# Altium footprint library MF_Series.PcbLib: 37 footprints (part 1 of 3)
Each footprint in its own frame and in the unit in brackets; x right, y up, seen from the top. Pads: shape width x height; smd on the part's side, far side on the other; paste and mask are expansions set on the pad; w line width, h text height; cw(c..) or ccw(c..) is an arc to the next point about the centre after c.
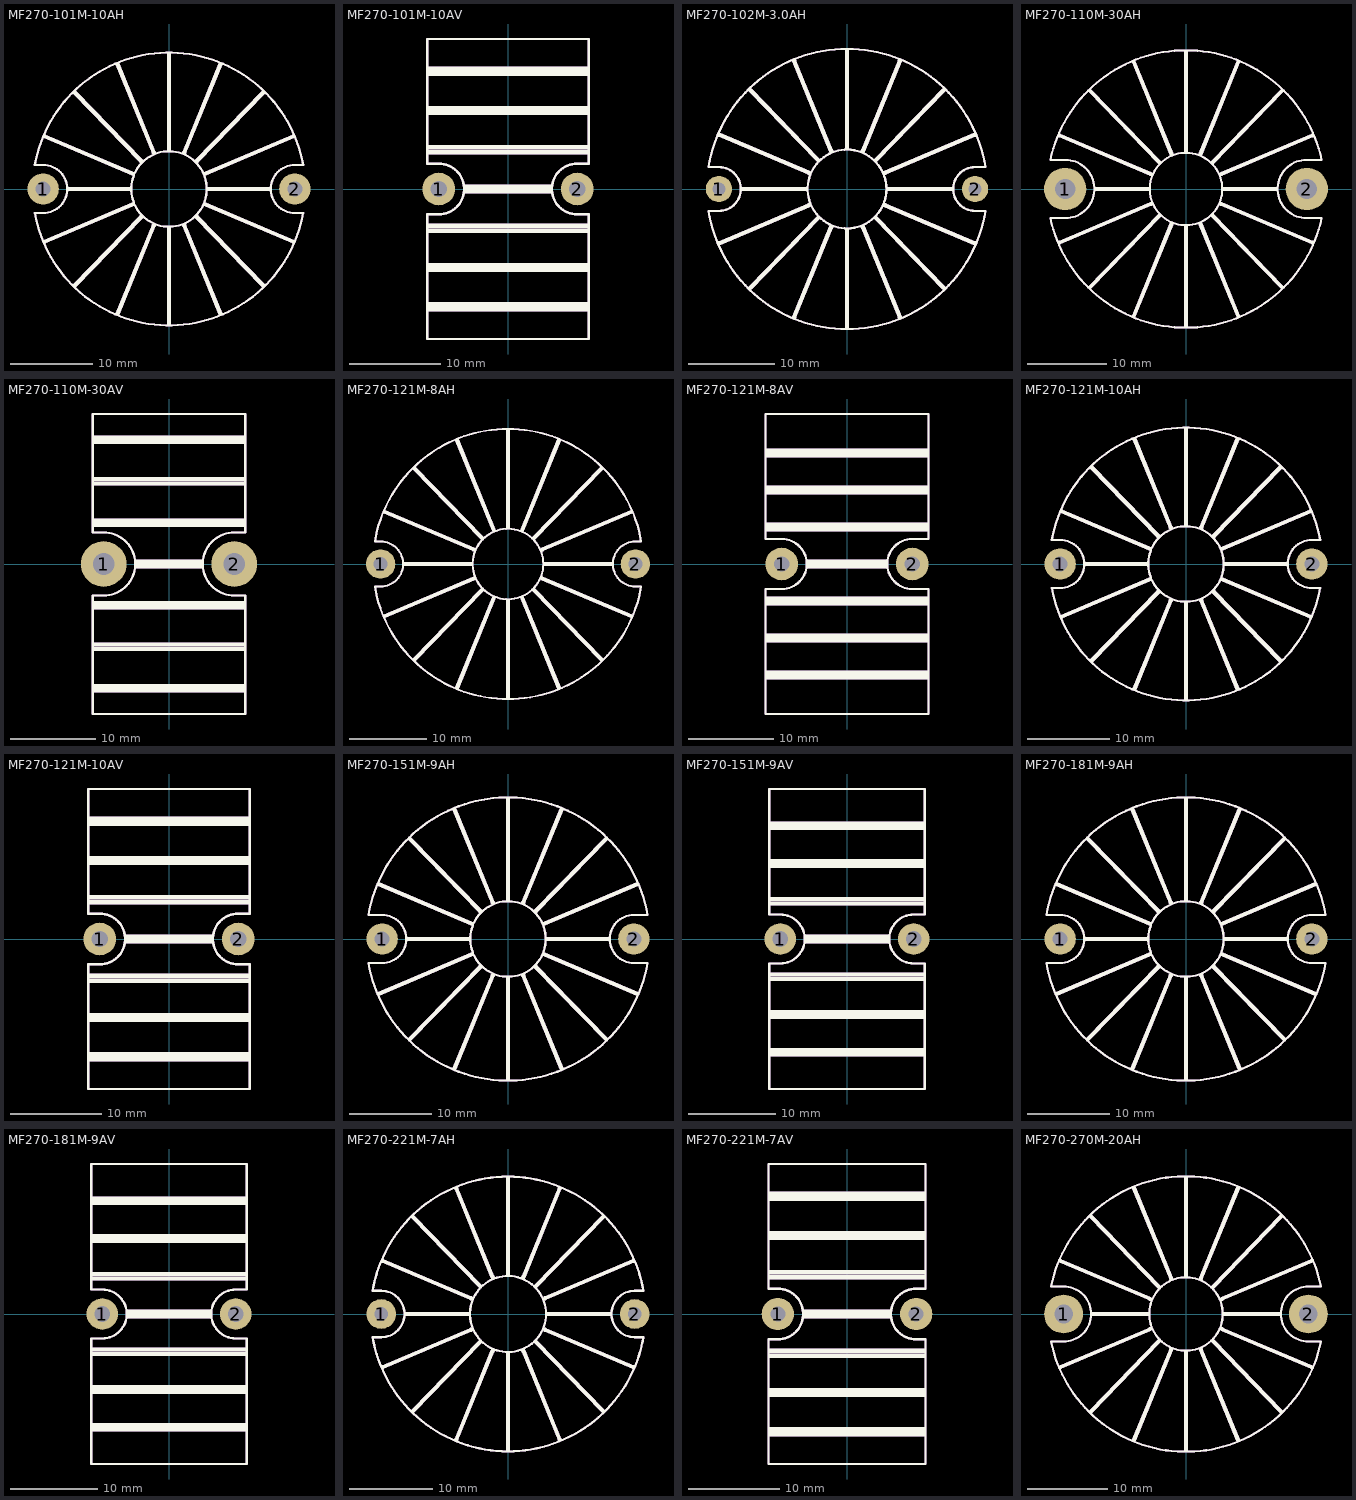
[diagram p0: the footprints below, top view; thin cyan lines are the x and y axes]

## MF270-101M-10AH [mil]
pads (2):
  round 150 hole 71: 1(-600,0) 2(600,0)
Top Overlay:
  circle w10: c0,0 r180
  lines w10: -639.75,-115 ccw(c0,0) 639.75,-115 600,-115 cw(c600,0) 600,115 639.77,114.84 ccw(c0,0) -639.77,114.84 -600,115 cw(c-600,0) -600,-115 -639.75,-115
  lines w19.68: -594.25,-251.8 -175.3,-74.28 ; -594.25,251.8 -175.3,74.28 ; -480,0 -185,0 ; -449.21,-459.18 -132.5,-132.5 ; -449.21,459.18 -132.5,132.5 ; -245,-595.01 -72.46,-173.99 ; -245,595.01 -72.46,173.99 ; 0,-645 0,-185 ; 0,185 0,645 ; 72.46,-173.99 245,-595.01 ; 72.46,173.99 245,595.01 ; 132.5,-132.5 449.21,-459.18 ; 132.5,132.5 449.21,459.18 ; 175.3,-74.28 594.25,-251.8 ; 175.3,74.28 594.25,251.8 ; 185,0 480,0
Mechanical 29:
  circle w10: c0,0 r180
  lines w10: -639.75,-115 ccw(c0,0) 639.75,-115 600,-115 cw(c600,0) 600,115 639.77,114.84 ccw(c0,0) -639.77,114.84 -600,115 cw(c-600,0) -600,-115 -639.75,-115
  lines w19.68: -594.25,-251.8 -175.3,-74.28 ; -594.25,251.8 -175.3,74.28 ; -480,0 -185,0 ; -449.21,-459.18 -132.5,-132.5 ; -449.21,459.18 -132.5,132.5 ; -245,-595.01 -72.46,-173.99 ; -245,595.01 -72.46,173.99 ; 0,-645 0,-185 ; 0,185 0,645 ; 72.46,-173.99 245,-595.01 ; 72.46,173.99 245,595.01 ; 132.5,-132.5 449.21,-459.18 ; 132.5,132.5 449.21,459.18 ; 175.3,-74.28 594.25,-251.8 ; 175.3,74.28 594.25,251.8 ; 185,0 480,0
  text "'.Designator'" at -290,145.17 h400

## MF270-101M-10AV [mil]
pads (2):
  round 142 hole 71: 1(-300,0) 2(300,0)
Top Overlay:
  lines w10: -350,-650 350,-650 350,-110 300,-110 cw(c300,0) 300,110 350,110 350,650 -350,650 -350,110 -300,110 cw(c-300,0) -300,-110 -350,-110 -350,-650
  lines w19.68: -345,-520 345,-520 ; -345,-500 345,-500 ; -345,-350 345,-350 ; -345,-330 345,-330 ; -345,-180 345,-180 ; -345,-160 345,-160 ; -345,160 345,160 ; -345,180 345,180 ; -345,330 345,330 ; -345,350 345,350 ; -345,500 345,500 ; -345,520 345,520 ; -185,-10 185,-10 ; -185,10 185,10
Mechanical 29:
  lines w10: -350,-650 350,-650 350,-110 300,-110 cw(c300,0) 300,110 350,110 350,650 -350,650 -350,110 -300,110 cw(c-300,0) -300,-110 -350,-110 -350,-650
  lines w19.68: -345,-520 345,-520 ; -345,-500 345,-500 ; -345,-350 345,-350 ; -345,-330 345,-330 ; -345,-180 345,-180 ; -345,-160 345,-160 ; -345,160 345,160 ; -345,180 345,180 ; -345,330 345,330 ; -345,350 345,350 ; -345,500 345,500 ; -345,520 345,520 ; -185,-10 185,-10 ; -185,10 185,10
  text "'.Designator'" at -1750,-64.83 h400

## MF270-102M-3.0AH [mil]
pads (2):
  round 120 hole 59: 1(-585,0) 2(585,0)
Top Overlay:
  circle w10: c0,0 r180
  lines w10: -632.04,-100.64 ccw(c0,0) 632.04,-100.64 ; -632.04,-100 -585,-100 ccw(c-585,0) -585,100 -632.04,100 ; -632.04,100.64 cw(c0,0) 632.04,100.64 ; 632.04,-100 585,-100 cw(c585,0) 585,100 632.04,100
  lines w19.68: -585.04,-247.9 -175.3,-74.28 ; -585.04,247.9 -175.3,74.28 ; -480,0 -185,0 ; -442.25,-452 -132.5,-132.5 ; -442.25,452 -132.5,132.5 ; -241.21,-585.75 -72.46,-173.99 ; -241.21,585.75 -72.46,173.99 ; 0,-635 0,-185 ; 0,185 0,635 ; 72.46,-173.99 241.21,-585.75 ; 72.46,173.99 241.21,585.75 ; 132.5,-132.5 442.25,-452 ; 132.5,132.5 442.25,452 ; 175.3,-74.28 585.04,-247.9 ; 175.3,74.28 585.04,247.9 ; 185,0 480,0
Mechanical 29:
  circle w10: c0,0 r180
  lines w10: -632.04,-100.64 ccw(c0,0) 632.04,-100.64 ; -632.04,-100 -585,-100 ccw(c-585,0) -585,100 -632.04,100 ; -632.04,100.64 cw(c0,0) 632.04,100.64 ; 632.04,-100 585,-100 cw(c585,0) 585,100 632.04,100
  lines w19.68: -585.04,-247.9 -175.3,-74.28 ; -585.04,247.9 -175.3,74.28 ; -480,0 -185,0 ; -442.25,-452 -132.5,-132.5 ; -442.25,452 -132.5,132.5 ; -241.21,-585.75 -72.46,-173.99 ; -241.21,585.75 -72.46,173.99 ; 0,-635 0,-185 ; 0,185 0,635 ; 72.46,-173.99 241.21,-585.75 ; 72.46,173.99 241.21,585.75 ; 132.5,-132.5 442.25,-452 ; 132.5,132.5 442.25,452 ; 175.3,-74.28 585.04,-247.9 ; 175.3,74.28 585.04,247.9 ; 185,0 480,0
  text "'.Designator'" at -290,145.17 h400

## MF270-110M-30AH [mil]
pads (2):
  round 210 hole 100: 1(-600,0) 2(600,0)
Top Overlay:
  circle w10: c0,0 r180
  lines w10: -673.56,-145.05 ccw(c0,0) 673.56,-145.05 ; -673.56,145.05 cw(c0,0) 673.56,145.05 ; -673.33,-145 -600,-145 ccw(c-600,0) -600,145 -673.33,145 ; 673.33,-145 600,-145 cw(c600,0) 600,145 673.33,145
  lines w19.68: -629.3,-266.65 -174.45,-73.92 ; -629.3,266.65 -175.3,74.28 ; -477.05,-487.9 -132.5,-132.5 ; -477.05,487.9 -132.5,132.5 ; -450,0 -185,0 ; -260.17,-632.02 -72.46,-173.99 ; -260.17,632.02 -72.46,173.99 ; 0,-680 0,-185 ; 72.46,-173.99 260.17,-632.02 ; 72.46,173.99 260.17,632.02 ; 132.5,-132.5 477.05,-487.9 ; 132.5,132.5 477.05,487.9 ; 174.45,-73.92 629.3,-266.65 ; 175.3,74.28 629.3,266.65 ; 185,0 450,0 ; 0,185 0,680 0,185
Mechanical 29:
  circle w10: c0,0 r180
  lines w10: -673.56,-145.05 ccw(c0,0) 673.56,-145.05 ; -673.56,145.05 cw(c0,0) 673.56,145.05 ; -673.33,-145 -600,-145 ccw(c-600,0) -600,145 -673.33,145 ; 673.33,-145 600,-145 cw(c600,0) 600,145 673.33,145
  lines w19.68: -629.3,-266.65 -174.45,-73.92 ; -629.3,266.65 -175.3,74.28 ; -477.05,-487.9 -132.5,-132.5 ; -477.05,487.9 -132.5,132.5 ; -450,0 -185,0 ; -260.17,-632.02 -72.46,-173.99 ; -260.17,632.02 -72.46,173.99 ; 0,-680 0,-185 ; 72.46,-173.99 260.17,-632.02 ; 72.46,173.99 260.17,632.02 ; 132.5,-132.5 477.05,-487.9 ; 132.5,132.5 477.05,487.9 ; 174.45,-73.92 629.3,-266.65 ; 175.3,74.28 629.3,266.65 ; 185,0 450,0 ; 0,185 0,680 0,185
  text "'.Designator'" at -290,145.17 h400

## MF270-110M-30AV [mil]
pads (2):
  round 210 hole 100: 1(-300,0) 2(300,0)
Top Overlay:
  lines w10: -350,-689 -350,-145 -300,-145 ccw(c-300,0) -300,145 -350,145 -350,689 350,689 350,145 300,145 ccw(c300,0) 300,-145 350,-145 350,-689 -350,-689
  lines w19.68: -345,-580 345,-580 ; -345,-560 345,-560 ; -345,-390 345,-390 ; -345,-370 345,-370 ; -345,-200 345,-200 ; -345,-180 345,-180 ; -345,180 345,180 ; -345,200 345,200 ; -345,370 345,370 ; -345,390 345,390 ; -345,560 345,560 ; -345,580 345,580 ; -150,-10 150,-10 ; -150,10 150,10
Mechanical 29:
  lines w10: -350,-689 -350,-145 -300,-145 ccw(c-300,0) -300,145 -350,145 -350,689 350,689 350,145 300,145 ccw(c300,0) 300,-145 350,-145 350,-689 -350,-689
  lines w19.68: -345,-580 345,-580 ; -345,-560 345,-560 ; -345,-390 345,-390 ; -345,-370 345,-370 ; -345,-200 345,-200 ; -345,-180 345,-180 ; -345,180 345,180 ; -345,200 345,200 ; -345,370 345,370 ; -345,390 345,390 ; -345,560 345,560 ; -345,580 345,580 ; -150,-10 150,-10 ; -150,10 150,10
  text "'.Designator'" at -1750,-64.83 h400

## MF270-121M-8AH [mil]
pads (2):
  round 150 hole 71: 1(-650,0) 2(650,0)
Top Overlay:
  circle w10: c0,0 r180
  lines w10: -679.33,-115.01 ccw(c0,0) 679.26,-115.46 ; -679.32,115.07 cw(c0,0) 679.32,115.07 ; -679.26,-115 -650,-115 ccw(c-650,0) -650,115 -678.92,115 ; 678.92,115 650,115 ccw(c650,0) 650,-115 679.26,-115
  lines w19.68: -629.3,-266.65 -174.45,-73.92 ; -629.3,266.65 -175.3,74.28 ; -530,0 -185,0 ; -477.05,-487.9 -132.5,-132.5 ; -477.05,487.9 -132.5,132.5 ; -260.17,-632.02 -72.46,-173.99 ; -260.17,632.02 -72.46,173.99 ; 0,-680 0,-185 ; 72.46,-173.99 260.17,-632.02 ; 72.46,173.99 260.17,632.02 ; 132.5,-132.5 477.05,-487.9 ; 132.5,132.5 477.05,487.9 ; 174.45,-73.92 629.3,-266.65 ; 175.3,74.28 629.3,266.65 ; 185,0 530,0 ; 0,185 0,680 0,185
Mechanical 29:
  circle w10: c0,0 r180
  lines w10: -679.33,-115.01 ccw(c0,0) 679.26,-115.46 ; -679.32,115.07 cw(c0,0) 679.32,115.07 ; -679.26,-115 -650,-115 ccw(c-650,0) -650,115 -678.92,115 ; 678.92,115 650,115 ccw(c650,0) 650,-115 679.26,-115
  lines w19.68: -629.3,-266.65 -174.45,-73.92 ; -629.3,266.65 -175.3,74.28 ; -530,0 -185,0 ; -477.05,-487.9 -132.5,-132.5 ; -477.05,487.9 -132.5,132.5 ; -260.17,-632.02 -72.46,-173.99 ; -260.17,632.02 -72.46,173.99 ; 0,-680 0,-185 ; 72.46,-173.99 260.17,-632.02 ; 72.46,173.99 260.17,632.02 ; 132.5,-132.5 477.05,-487.9 ; 132.5,132.5 477.05,487.9 ; 174.45,-73.92 629.3,-266.65 ; 175.3,74.28 629.3,266.65 ; 185,0 530,0 ; 0,185 0,680 0,185
  text "'.Designator'" at -290,145.17 h400

## MF270-121M-8AV [mil]
pads (2):
  round 150 hole 71: 1(-300,0) 2(300,0)
Top Overlay:
  lines w10: -375,-689 -375,-115 -300,-115 ccw(c-300,0) -300,115 -375,115 -375,689 375,689 375,115 300,115 ccw(c300,0) 300,-115 375,-115 375,-689 -375,-689
  lines w19.68: -370,-520 370,-520 ; -370,-500 370,-500 ; -370,-350 370,-350 ; -370,-330 370,-330 ; -370,-180 370,-180 ; -370,-160 370,-160 ; -370,160 370,160 ; -370,180 370,180 ; -370,330 370,330 ; -370,350 370,350 ; -370,500 370,500 ; -370,520 370,520 ; -180,-10 180,-10 ; -180,10 180,10
Mechanical 29:
  lines w10: -375,-689 -375,-115 -300,-115 ccw(c-300,0) -300,115 -375,115 -375,689 375,689 375,115 300,115 ccw(c300,0) 300,-115 375,-115 375,-689 -375,-689
  lines w19.68: -370,-520 370,-520 ; -370,-500 370,-500 ; -370,-350 370,-350 ; -370,-330 370,-330 ; -370,-180 370,-180 ; -370,-160 370,-160 ; -370,160 370,160 ; -370,180 370,180 ; -370,330 370,330 ; -370,350 370,350 ; -370,500 370,500 ; -370,520 370,520 ; -180,-10 180,-10 ; -180,10 180,10
  text "'.Designator'" at -1750,-64.83 h400

## MF270-121M-10AH [mil]
pads (2):
  round 150 hole 71: 1(-600,0) 2(600,0)
Top Overlay:
  circle w10: c0,0 r180
  lines w10: -639.75,-115 ccw(c0,0) 639.75,-115 600,-115 cw(c600,0) 600,115 639.77,114.84 ccw(c0,0) -639.77,114.84 -600,115 cw(c-600,0) -600,-115 -639.75,-115
  lines w19.68: -594.25,-251.8 -175.3,-74.28 ; -594.25,251.8 -175.3,74.28 ; -480,0 -185,0 ; -449.21,-459.18 -132.5,-132.5 ; -449.21,459.18 -132.5,132.5 ; -245,-595.01 -72.46,-173.99 ; -245,595.01 -72.46,173.99 ; 0,-645 0,-185 ; 0,185 0,645 ; 72.46,-173.99 245,-595.01 ; 72.46,173.99 245,595.01 ; 132.5,-132.5 449.21,-459.18 ; 132.5,132.5 449.21,459.18 ; 175.3,-74.28 594.25,-251.8 ; 175.3,74.28 594.25,251.8 ; 185,0 480,0
Mechanical 29:
  circle w10: c0,0 r180
  lines w10: -639.75,-115 ccw(c0,0) 639.75,-115 600,-115 cw(c600,0) 600,115 639.77,114.84 ccw(c0,0) -639.77,114.84 -600,115 cw(c-600,0) -600,-115 -639.75,-115
  lines w19.68: -594.25,-251.8 -175.3,-74.28 ; -594.25,251.8 -175.3,74.28 ; -480,0 -185,0 ; -449.21,-459.18 -132.5,-132.5 ; -449.21,459.18 -132.5,132.5 ; -245,-595.01 -72.46,-173.99 ; -245,595.01 -72.46,173.99 ; 0,-645 0,-185 ; 0,185 0,645 ; 72.46,-173.99 245,-595.01 ; 72.46,173.99 245,595.01 ; 132.5,-132.5 449.21,-459.18 ; 132.5,132.5 449.21,459.18 ; 175.3,-74.28 594.25,-251.8 ; 175.3,74.28 594.25,251.8 ; 185,0 480,0
  text "'.Designator'" at -290,145.17 h400

## MF270-121M-10AV [mil]
pads (2):
  round 142 hole 71: 1(-300,0) 2(300,0)
Top Overlay:
  lines w10: -350,-650 -350,-110 -300,-110 ccw(c-300,0) -300,110 -350,110 -350,650 350,650 350,110 300,110 ccw(c300,0) 300,-110 350,-110 350,-650 -350,-650
  lines w19.68: -345,-520 345,-520 ; -345,-500 345,-500 ; -345,-350 345,-350 ; -345,-330 345,-330 ; -345,-180 345,-180 ; -345,-160 345,-160 ; -345,160 345,160 ; -345,180 345,180 ; -345,330 345,330 ; -345,350 345,350 ; -345,500 345,500 ; -345,520 345,520 ; -185,-10 185,-10 ; -185,10 185,10
Mechanical 29:
  lines w10: -350,-650 -350,-110 -300,-110 ccw(c-300,0) -300,110 -350,110 -350,650 350,650 350,110 300,110 ccw(c300,0) 300,-110 350,-110 350,-650 -350,-650
  lines w19.68: -345,-520 345,-520 ; -345,-500 345,-500 ; -345,-350 345,-350 ; -345,-330 345,-330 ; -345,-180 345,-180 ; -345,-160 345,-160 ; -345,160 345,160 ; -345,180 345,180 ; -345,330 345,330 ; -345,350 345,350 ; -345,500 345,500 ; -345,520 345,520 ; -185,-10 185,-10 ; -185,10 185,10
  text "'.Designator'" at -1750,-64.83 h400

## MF270-151M-9AH [mil]
pads (2):
  round 150 hole 71: 1(-600,0) 2(600,0)
Top Overlay:
  circle w10: c0,0 r180
  lines w10: -665.12,115.06 cw(c0,0) 665.12,115.06 ; -664.79,115 -600,115 cw(c-600,0) -600,-115 -665.13,-115 ccw(c0,0) 665.13,-115 600,-115 cw(c600,0) 600,115 664.79,115
  lines w19.68: -617.26,-261.55 -175.3,-74.28 ; -617.26,261.55 -175.3,74.28 ; -480,0 -185,0 ; -466.61,-477.13 -132.5,-132.5 ; -466.61,477.13 -132.5,132.5 ; -254.48,-618.14 -72.46,-173.99 ; -254.48,618.14 -72.46,173.99 ; 0,-665 0,-185 ; 0,185 0,665 ; 72.46,-173.99 254.48,-618.14 ; 72.46,173.99 254.48,618.14 ; 132.5,-132.5 466.61,-477.13 ; 132.5,132.5 466.61,477.13 ; 175.3,-74.28 617.26,-261.55 ; 175.3,74.28 617.26,261.55 ; 185,0 480,0
Mechanical 29:
  circle w10: c0,0 r180
  lines w10: -665.12,115.06 cw(c0,0) 665.12,115.06 ; -664.79,115 -600,115 cw(c-600,0) -600,-115 -665.13,-115 ccw(c0,0) 665.13,-115 600,-115 cw(c600,0) 600,115 664.79,115
  lines w19.68: -617.26,-261.55 -175.3,-74.28 ; -617.26,261.55 -175.3,74.28 ; -480,0 -185,0 ; -466.61,-477.13 -132.5,-132.5 ; -466.61,477.13 -132.5,132.5 ; -254.48,-618.14 -72.46,-173.99 ; -254.48,618.14 -72.46,173.99 ; 0,-665 0,-185 ; 0,185 0,665 ; 72.46,-173.99 254.48,-618.14 ; 72.46,173.99 254.48,618.14 ; 132.5,-132.5 466.61,-477.13 ; 132.5,132.5 466.61,477.13 ; 175.3,-74.28 617.26,-261.55 ; 175.3,74.28 617.26,261.55 ; 185,0 480,0
  text "'.Designator'" at -290,145.17 h400

## MF270-151M-9AV [mil]
pads (2):
  round 142 hole 71: 1(-300,0) 2(300,0)
Top Overlay:
  lines w10: -350,-675 -350,-110 -300,-110 ccw(c-300,0) -300,110 -350,110 -350,675 350,675 350,110 300,110 ccw(c300,0) 300,-110 350,-110 350,-675 -350,-675
  lines w19.68: -345,-520 345,-520 ; -345,-500 345,-500 ; -345,-350 345,-350 ; -345,-330 345,-330 ; -345,-180 345,-180 ; -345,-160 345,-160 ; -345,160 345,160 ; -345,180 345,180 ; -345,330 345,330 ; -345,350 345,350 ; -345,500 345,500 ; -345,520 345,520 ; -185,-10 185,-10 ; -185,10 185,10
Mechanical 29:
  lines w10: -350,-675 -350,-110 -300,-110 ccw(c-300,0) -300,110 -350,110 -350,675 350,675 350,110 300,110 ccw(c300,0) 300,-110 350,-110 350,-675 -350,-675
  lines w19.68: -345,-520 345,-520 ; -345,-500 345,-500 ; -345,-350 345,-350 ; -345,-330 345,-330 ; -345,-180 345,-180 ; -345,-160 345,-160 ; -345,160 345,160 ; -345,180 345,180 ; -345,330 345,330 ; -345,350 345,350 ; -345,500 345,500 ; -345,520 345,520 ; -185,-10 185,-10 ; -185,10 185,10
  text "'.Designator'" at -1750,-64.83 h400

## MF270-181M-9AH [mil]
pads (2):
  round 150 hole 71: 1(-600,0) 2(600,0)
Top Overlay:
  circle w10: c0,0 r180
  lines w10: -665.12,115.06 cw(c0,0) 665.12,115.06 ; -664.79,115 -600,115 cw(c-600,0) -600,-115 -665.13,-115 ccw(c0,0) 665.13,-115 600,-115 cw(c600,0) 600,115 664.79,115
  lines w19.68: -617.26,-261.55 -175.3,-74.28 ; -617.26,261.55 -175.3,74.28 ; -480,0 -185,0 ; -466.61,-477.13 -132.5,-132.5 ; -466.61,477.13 -132.5,132.5 ; -254.48,-618.14 -72.46,-173.99 ; -254.48,618.14 -72.46,173.99 ; 0,-665 0,-185 ; 0,185 0,665 ; 72.46,-173.99 254.48,-618.14 ; 72.46,173.99 254.48,618.14 ; 132.5,-132.5 466.61,-477.13 ; 132.5,132.5 466.61,477.13 ; 175.3,-74.28 617.26,-261.55 ; 175.3,74.28 617.26,261.55 ; 185,0 480,0
Mechanical 29:
  circle w10: c0,0 r180
  lines w10: -665.12,115.06 cw(c0,0) 665.12,115.06 ; -664.79,115 -600,115 cw(c-600,0) -600,-115 -665.13,-115 ccw(c0,0) 665.13,-115 600,-115 cw(c600,0) 600,115 664.79,115
  lines w19.68: -617.26,-261.55 -175.3,-74.28 ; -617.26,261.55 -175.3,74.28 ; -480,0 -185,0 ; -466.61,-477.13 -132.5,-132.5 ; -466.61,477.13 -132.5,132.5 ; -254.48,-618.14 -72.46,-173.99 ; -254.48,618.14 -72.46,173.99 ; 0,-665 0,-185 ; 0,185 0,665 ; 72.46,-173.99 254.48,-618.14 ; 72.46,173.99 254.48,618.14 ; 132.5,-132.5 466.61,-477.13 ; 132.5,132.5 466.61,477.13 ; 175.3,-74.28 617.26,-261.55 ; 175.3,74.28 617.26,261.55 ; 185,0 480,0
  text "'.Designator'" at -290,145.17 h400

## MF270-181M-9AV [mil]
pads (2):
  round 142 hole 71: 1(-300,0) 2(300,0)
Top Overlay:
  lines w10: -350,-675 350,-675 350,-110 300,-110 cw(c300,0) 300,110 350,110 350,675 -350,675 -350,110 -300,110 cw(c-300,0) -300,-110 -350,-110 -350,-675
  lines w19.68: -345,-520 345,-520 ; -345,-500 345,-500 ; -345,-350 345,-350 ; -345,-330 345,-330 ; -345,-180 345,-180 ; -345,-160 345,-160 ; -345,160 345,160 ; -345,180 345,180 ; -345,330 345,330 ; -345,350 345,350 ; -345,500 345,500 ; -345,520 345,520 ; -185,-10 185,-10 ; -185,10 185,10
Mechanical 29:
  lines w10: -350,-675 350,-675 350,-110 300,-110 cw(c300,0) 300,110 350,110 350,675 -350,675 -350,110 -300,110 cw(c-300,0) -300,-110 -350,-110 -350,-675
  lines w19.68: -345,-520 345,-520 ; -345,-500 345,-500 ; -345,-350 345,-350 ; -345,-330 345,-330 ; -345,-180 345,-180 ; -345,-160 345,-160 ; -345,160 345,160 ; -345,180 345,180 ; -345,330 345,330 ; -345,350 345,350 ; -345,500 345,500 ; -345,520 345,520 ; -185,-10 185,-10 ; -185,10 185,10
  text "'.Designator'" at -1750,-64.83 h400

## MF270-221M-7AH [mil]
pads (2):
  round 140 hole 65: 1(-600,0) 2(600,0)
Top Overlay:
  circle w10: c0,0 r180
  lines w10: -640.55,109.84 -600,110 cw(c-600,0) -600,-110 -640.62,-110 ccw(c0,0) 640.53,-110.57 ; -640.55,110.43 cw(c0,0) 640.55,110.44 ; 640.53,-110 600,-110 cw(c600,0) 600,110 640.55,109.84
  lines w19.68: -594.25,-251.8 -175.3,-74.28 ; -594.25,251.8 -175.3,74.28 ; -485,0 -185,0 ; -449.21,-459.18 -132.5,-132.5 ; -449.21,459.18 -132.5,132.5 ; -245,-595.01 -72.46,-173.99 ; -245,595.01 -72.46,173.99 ; 0,-645 0,-185 ; 0,185 0,645 ; 72.46,-173.99 245,-595.01 ; 72.46,173.99 245,595.01 ; 132.5,-132.5 449.21,-459.18 ; 132.5,132.5 449.21,459.18 ; 175.3,-74.28 594.25,-251.8 ; 175.3,74.28 594.25,251.8 ; 185,0 485,0
Mechanical 29:
  circle w10: c0,0 r180
  lines w10: -640.55,109.84 -600,110 cw(c-600,0) -600,-110 -640.62,-110 ccw(c0,0) 640.53,-110.57 ; -640.55,110.43 cw(c0,0) 640.55,110.44 ; 640.53,-110 600,-110 cw(c600,0) 600,110 640.55,109.84
  lines w19.68: -594.25,-251.8 -175.3,-74.28 ; -594.25,251.8 -175.3,74.28 ; -485,0 -185,0 ; -449.21,-459.18 -132.5,-132.5 ; -449.21,459.18 -132.5,132.5 ; -245,-595.01 -72.46,-173.99 ; -245,595.01 -72.46,173.99 ; 0,-645 0,-185 ; 0,185 0,645 ; 72.46,-173.99 245,-595.01 ; 72.46,173.99 245,595.01 ; 132.5,-132.5 449.21,-459.18 ; 132.5,132.5 449.21,459.18 ; 175.3,-74.28 594.25,-251.8 ; 175.3,74.28 594.25,251.8 ; 185,0 485,0
  text "'.Designator'" at -290,145.17 h400

## MF270-221M-7AV [mil]
pads (2):
  round 140 hole 65: 1(-300,0) 2(300,0)
Top Overlay:
  lines w10: -340,-650 -340,-110 -300,-110 ccw(c-300,0) -300,110 -340,110 -340,650 340,650 340,110 300,110 ccw(c300,0) 300,-110 340,-110 340,-650 -340,-650
  lines w19.68: -335,-520 335,-520 ; -335,-500 335,-500 ; -335,-350 335,-350 ; -335,-330 335,-330 ; -335,-180 335,-180 ; -335,-160 335,-160 ; -335,160 335,160 ; -335,180 335,180 ; -335,330 335,330 ; -335,350 335,350 ; -335,500 335,500 ; -335,520 335,520 ; -185,-10 185,-10 ; -185,10 185,10
Mechanical 29:
  lines w10: -340,-650 -340,-110 -300,-110 ccw(c-300,0) -300,110 -340,110 -340,650 340,650 340,110 300,110 ccw(c300,0) 300,-110 340,-110 340,-650 -340,-650
  lines w19.68: -335,-520 335,-520 ; -335,-500 335,-500 ; -335,-350 335,-350 ; -335,-330 335,-330 ; -335,-180 335,-180 ; -335,-160 335,-160 ; -335,160 335,160 ; -335,180 335,180 ; -335,330 335,330 ; -335,350 335,350 ; -335,500 335,500 ; -335,520 335,520 ; -185,-10 185,-10 ; -185,10 185,10
  text "'.Designator'" at -1750,-64.83 h400

## MF270-270M-20AH [mil]
pads (2):
  round 190 hole 91: 1(-600,0) 2(600,0)
Top Overlay:
  circle w10: c0,0 r180
  lines w10: -661.36,-135 ccw(c0,0) 661.36,-135 600,-135 cw(c600,0) 600,135 661.36,135 ccw(c0,0) -661.36,135 -600,135 cw(c-600,0) -600,-135 -661.36,-135
  lines w19.68: -617.26,-261.55 -175.3,-74.28 ; -617.26,261.55 -175.3,74.28 ; -466.61,-477.13 -132.5,-132.5 ; -466.61,477.13 -132.5,132.5 ; -460,0 -185,0 ; -254.48,-618.14 -72.46,-173.99 ; -254.48,618.14 -72.46,173.99 ; 0,-665 0,-185 ; 0,185 0,665 ; 72.46,-173.99 254.48,-618.14 ; 72.46,173.99 254.48,618.14 ; 132.5,-132.5 466.61,-477.13 ; 132.5,132.5 466.61,477.13 ; 175.3,-74.28 617.26,-261.55 ; 175.3,74.28 617.26,261.55 ; 185,0 460,0
Mechanical 29:
  circle w10: c0,0 r180
  lines w10: -661.36,-135 ccw(c0,0) 661.36,-135 600,-135 cw(c600,0) 600,135 661.36,135 ccw(c0,0) -661.36,135 -600,135 cw(c-600,0) -600,-135 -661.36,-135
  lines w19.68: -617.26,-261.55 -175.3,-74.28 ; -617.26,261.55 -175.3,74.28 ; -466.61,-477.13 -132.5,-132.5 ; -466.61,477.13 -132.5,132.5 ; -460,0 -185,0 ; -254.48,-618.14 -72.46,-173.99 ; -254.48,618.14 -72.46,173.99 ; 0,-665 0,-185 ; 0,185 0,665 ; 72.46,-173.99 254.48,-618.14 ; 72.46,173.99 254.48,618.14 ; 132.5,-132.5 466.61,-477.13 ; 132.5,132.5 466.61,477.13 ; 175.3,-74.28 617.26,-261.55 ; 175.3,74.28 617.26,261.55 ; 185,0 460,0
  text "'.Designator'" at -290,145.17 h400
